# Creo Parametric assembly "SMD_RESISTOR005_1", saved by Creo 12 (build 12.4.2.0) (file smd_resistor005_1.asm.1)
Units: Custom; MM, KILOGRAM, SECS

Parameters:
  PTC_WM_ITERATION = "0"
  PTC_WM_VERSION = "-.0"
  PTC_WM_LIFECYCLE_STATE = "In Work"
  PTC_WM_LIFECYCLE = "MO_CADDocument"
  PTC_WM_CREATED_BY = "Maximilian Roepper (Z0017RMS: MO)"
  PTC_WM_CREATED_ON = "18-Sep-26 11:36:42 AM"
  PTC_WM_MODIFIED_BY = "Maximilian Roepper (Z0017RMS: MO)"
  PTC_WM_MODIFIED_ON = "18-Sep-26 11:36:46 AM"
  PDMLINKNUMBER = "PDM000071455163"
  PTC_WM_NUMBER = "PDM000071455163"

Other parameters: WEIGHT, WEIGHT_FACTOR, WEIGHT_ADD, MC_ERRORS, SUPPLIER

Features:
  1. coordinate system
  2. imported feature
  3. component "BODY006_1"
  4. component "CONTACT022_1"
  5. component "CONTACT023_1"
  6. component "LABEL004_1"
  7. component "PART019_1"

Other named items: DRW_VIEW_ORG, ROUGH-GROB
